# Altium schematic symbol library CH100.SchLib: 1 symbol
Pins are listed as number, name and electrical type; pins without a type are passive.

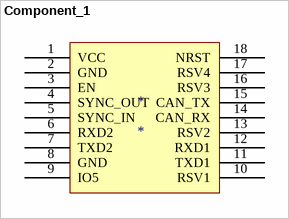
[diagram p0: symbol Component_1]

## Component_1
designator *
pins: 1 VCC, 2 GND, 3 EN, 4 SYNC_OUT, 5 SYNC_IN, 6 RXD2, 7 TXD2, 8 GND, 9 IO5, 10 RSV1, 11 TXD1, 12 RXD1, 13 RSV2, 14 CAN_RX, 15 CAN_TX, 16 RSV3, 17 RSV4, 18 NRST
